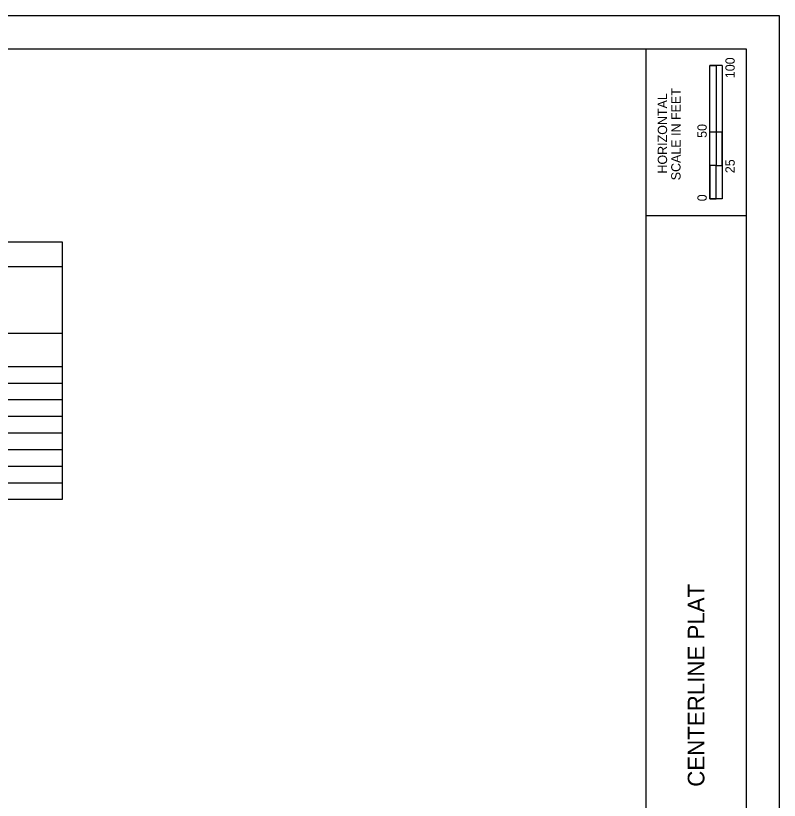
# Model space of a CAD drawing. Extents: x 1.8 to 35.8, y 1.7 to 23.7.
# Drawn here: x 24.34 to 35.81, y 11.94 to 23.72 of the extents above; entities that cross this region are included whole.
import ezdxf

# ---------------------------------------------------------------- set-up
doc = ezdxf.new("R2010")
doc.units = 0
for name, color, linetype in [('SN_X_Public', 7, 'Continuous'), ('SV_X_Mon_Cells_Found', 7, 'Continuous'), ('SV_X_Shot_Marker', 7, 'Continuous'), ('VG_X_Cells', 7, 'Continuous')]:
    doc.layers.add(name, color=color, linetype=linetype)

msp = doc.modelspace()

# ---------------------------------------------------------------- linework, layer by layer
at = {"layer": 'SN_X_Public'}
for p, q in [((11.941, 19.957), (25.041, 19.957)), ((11.941, 18.957), (25.041, 18.957)), ((11.941, 18.457), (25.041, 18.457)), ((11.941, 18.207), (25.041, 18.207)), ((11.941, 17.957), (25.041, 17.957)), ((11.941, 17.707), (25.041, 17.707)), ((11.941, 17.457), (25.041, 17.457)), ((11.941, 17.207), (25.041, 17.207)), ((11.941, 16.957), (25.041, 16.957)), ((11.941, 16.707), (25.041, 16.707))]:
    msp.add_line(p, q, dxfattribs=at)
msp.add_lwpolyline([(11.941, 20.328), (25.041, 20.328), (25.041, 16.457), (11.941, 16.457)], close=True, dxfattribs=at)
at = {"layer": 'SV_X_Mon_Cells_Found'}
msp.add_lwpolyline([(1.808, 1.721), (35.808, 1.721), (35.808, 23.721), (1.808, 23.721)], close=True, dxfattribs=at)
at = {"layer": 'SV_X_Shot_Marker'}
for p, q in [((33.808, 2.221), (33.808, 23.221)), ((33.808, 20.721), (35.308, 20.721))]:
    msp.add_line(p, q, dxfattribs=at)
msp.add_lwpolyline([(3.308, 23.221), (35.308, 23.221), (35.308, 2.221), (3.308, 2.221)], close=True, dxfattribs=at)
at = {"layer": 'VG_X_Cells'}
for p, q in [((34.764, 20.971), (34.764, 22.971)), ((34.952, 22.971), (34.764, 22.971)), ((34.764, 21.971), (34.764, 22.971)), ((34.764, 22.971), (34.858, 22.971)), ((34.858, 22.971), (34.858, 21.971)), ((34.858, 22.971), (34.858, 22.971)), ((34.952, 22.971), (34.952, 20.971)), ((34.858, 21.971), (34.764, 21.971)), ((34.951, 21.971), (34.858, 21.971)), ((34.858, 21.971), (34.858, 21.471)), ((34.951, 21.471), (34.951, 21.971)), ((34.858, 21.471), (34.764, 21.471)), ((34.764, 21.471), (34.764, 20.971)), ((34.858, 21.471), (34.951, 21.471)), ((34.858, 20.971), (34.858, 21.471)), ((34.952, 20.971), (34.764, 20.971)), ((34.764, 20.971), (34.858, 20.971))]:
    msp.add_line(p, q, dxfattribs=at)

# ---------------------------------------------------------------- texts
for s, height, p in [('100', 0.14, (35.138, 22.783)), ('SCALE IN FEET', 0.14, (34.325, 21.25)), ('HORIZONTAL', 0.14, (34.123, 21.351)), ('50', 0.14, (34.718, 21.887)), ('25', 0.14, (35.138, 21.357)), ('0', 0.14, (34.718, 20.935)), ('CENTERLINE PLAT', 0.25, (34.683, 12.146))]:
    msp.add_text(s, height=height, rotation=90, dxfattribs=at).set_placement(p)

doc.saveas('drawing.dxf')
